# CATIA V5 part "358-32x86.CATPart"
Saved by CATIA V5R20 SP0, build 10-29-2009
Part number: 358-32X86
Definition: NONE
Nomenclature: 358-32X86
Source: Unknown
Description: 358-32X86
Bounding box of the stored display mesh (mm): x -17 to 69, y -22.5 to 22.5, z -22.5 to 22.5
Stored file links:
  C:\Users\Utente\Desktop\IO LAVORO\3D X SITO CF\X SITO\PLASTICA\358\358-32x86.CATPart

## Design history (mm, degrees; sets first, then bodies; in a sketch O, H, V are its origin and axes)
Body1 "358-32X86" (main body)
  Solid1: solid without history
